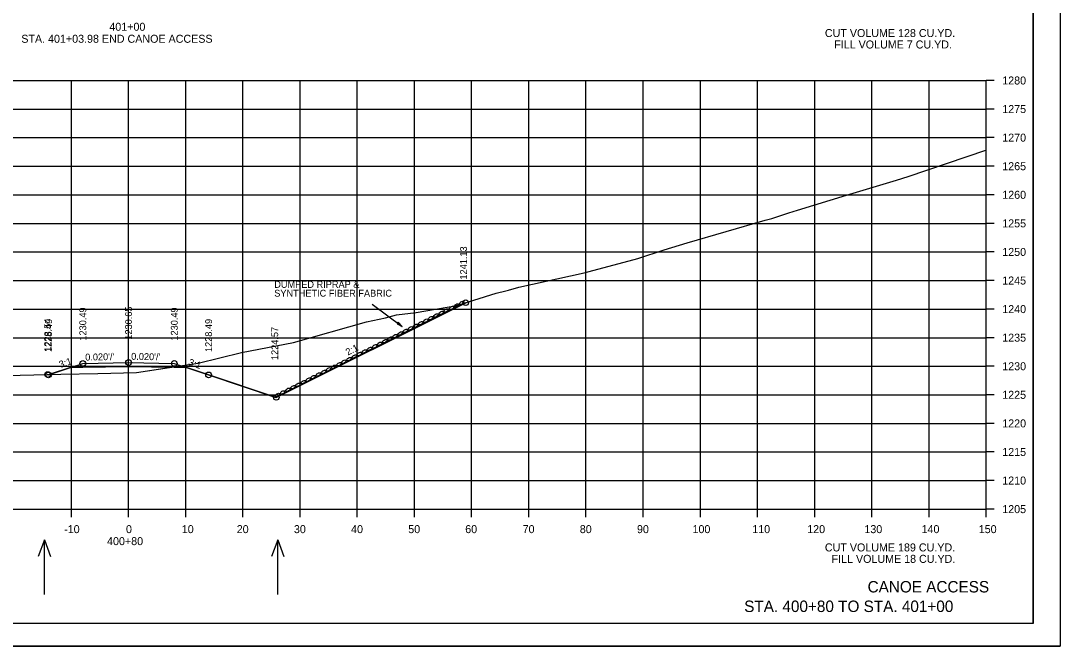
# Model space of a CAD drawing. Extents: x 1406028 to 1412453, y 321733 to 325986.
# Drawn here: x 1411764.4 to 1411946.2, y 322684.9 to 322794.4 of the extents above; entities that cross this region are included whole.
import ezdxf

# ---------------------------------------------------------------- set-up
doc = ezdxf.new("R2010")
doc.units = 0
for name, color, linetype in [('R_Alt Surface', 7, 'Continuous'), ('R_Axis', 7, 'Continuous'), ('R_Axis Annot', 7, 'Continuous'), ('R_Border', 7, 'Continuous'), ('R_Contours', 7, 'Continuous'), ('R_Draft', 7, 'Continuous'), ('R_Exist Surface', 7, 'Continuous'), ('R_Fin Surface', 7, 'Continuous'), ('R_Fin Surface Annot', 7, 'Continuous'), ('R_Grid', 7, 'Continuous'), ('R_No Plot', 7, 'Continuous'), ('R_Water Annot', 7, 'Continuous')]:
    doc.layers.add(name, color=color, linetype=linetype)

msp = doc.modelspace()

# ---------------------------------------------------------------- linework, layer by layer
for points in [[(1411809.08, 322728.49), (1411842.2, 322745.05)], [(1411797.24, 322732.44), (1411809.08, 322728.49)]]:
    msp.add_lwpolyline(points)
at = {"layer": 'R_Alt Surface'}
msp.add_lwpolyline([(1411773.11, 322733.7), (1411775.24, 322733.75), (1411783.24, 322733.91), (1411791.24, 322733.75), (1411793.38, 322733.7)], dxfattribs=at)
at = {"layer": 'R_Axis'}
for p, q in [((1411933.24, 322708.93), (1411933.24, 322783.93)), ((1411934.64, 322783.93), (1411933.24, 322783.93)), ((1411934.64, 322778.93), (1411933.24, 322778.93)), ((1411934.64, 322773.93), (1411933.24, 322773.93)), ((1411934.64, 322768.93), (1411933.24, 322768.93)), ((1411934.64, 322763.93), (1411933.24, 322763.93)), ((1411934.64, 322758.93), (1411933.24, 322758.93)), ((1411934.64, 322753.93), (1411933.24, 322753.93)), ((1411934.64, 322748.93), (1411933.24, 322748.93)), ((1411934.64, 322743.93), (1411933.24, 322743.93)), ((1411934.64, 322738.93), (1411933.24, 322738.93)), ((1411934.64, 322733.93), (1411933.24, 322733.93)), ((1411934.64, 322728.93), (1411933.24, 322728.93)), ((1411934.64, 322723.93), (1411933.24, 322723.93)), ((1411934.64, 322718.93), (1411933.24, 322718.93)), ((1411934.64, 322713.93), (1411933.24, 322713.93)), ((1411633.24, 322708.93), (1411933.24, 322708.93)), ((1411773.24, 322707.53), (1411773.24, 322708.93)), ((1411783.24, 322707.53), (1411783.24, 322708.93)), ((1411793.24, 322707.53), (1411793.24, 322708.93)), ((1411803.24, 322707.53), (1411803.24, 322708.93)), ((1411813.24, 322707.53), (1411813.24, 322708.93)), ((1411823.24, 322707.53), (1411823.24, 322708.93)), ((1411833.24, 322707.53), (1411833.24, 322708.93)), ((1411843.24, 322707.53), (1411843.24, 322708.93)), ((1411853.24, 322707.53), (1411853.24, 322708.93)), ((1411863.24, 322707.53), (1411863.24, 322708.93)), ((1411873.24, 322707.53), (1411873.24, 322708.93)), ((1411883.24, 322707.53), (1411883.24, 322708.93)), ((1411893.24, 322707.53), (1411893.24, 322708.93)), ((1411903.24, 322707.53), (1411903.24, 322708.93)), ((1411913.24, 322707.53), (1411913.24, 322708.93)), ((1411923.24, 322707.53), (1411923.24, 322708.93)), ((1411933.24, 322707.53), (1411933.24, 322708.93)), ((1411934.64, 322708.93), (1411933.24, 322708.93))]:
    msp.add_line(p, q, dxfattribs=at)
at = {"layer": 'R_Border'}
for q in [(1411941.42, 322894.39), (1411625.24, 322688.93)]:
    msp.add_line((1411941.42, 322688.93), q, dxfattribs=at)
at = {"layer": 'R_Contours'}
for points in [[(1411790.72, 322733.78), (1411795.4, 322734.49), (1411802.97, 322736.34), (1411812.06, 322738.07), (1411824.86, 322741.68), (1411828.19, 322742.38), (1411830.12, 322742.9), (1411833.52, 322743.32), (1411840.64, 322744.57), (1411842.2, 322745.05), (1411809.08, 322728.49), (1411797.24, 322732.44), (1411793.38, 322733.73), (1411791.24, 322733.77)], [(1411769.35, 322732.47), (1411771.39, 322732.52), (1411777.87, 322732.66), (1411784.62, 322732.85), (1411790.72, 322733.78), (1411783.24, 322733.93), (1411775.24, 322733.77), (1411773.11, 322733.73)], [(1411769.15, 322732.47), (1411769.35, 322732.47), (1411769.24, 322732.44)]]:
    msp.add_lwpolyline(points, close=True, dxfattribs=at)
at = {"layer": 'R_Draft'}
for p, q in [((1411825.87, 322744.82), (1411831.1, 322740.9)), ((1411830.39, 322741.62), (1411830.21, 322741.38)), ((1411830.21, 322741.38), (1411831.1, 322740.9)), ((1411830.23, 322741.4), (1411830.97, 322741)), ((1411830.24, 322741.42), (1411830.83, 322741.11)), ((1411830.26, 322741.44), (1411830.7, 322741.21)), ((1411830.27, 322741.46), (1411830.56, 322741.31)), ((1411830.29, 322741.48), (1411830.43, 322741.41)), ((1411830.32, 322741.52), (1411830.43, 322741.41)), ((1411830.33, 322741.54), (1411830.56, 322741.31)), ((1411830.35, 322741.56), (1411830.7, 322741.21)), ((1411830.36, 322741.58), (1411830.83, 322741.11)), ((1411830.38, 322741.6), (1411830.97, 322741)), ((1411830.39, 322741.62), (1411831.1, 322740.9))]:
    msp.add_line(p, q, dxfattribs=at)
for centre in [(1411841.5, 322745.01), (1411837.9, 322743.26), (1411838.8, 322743.7), (1411839.7, 322744.13), (1411840.6, 322744.57), (1411834.32, 322741.46), (1411835.22, 322741.9), (1411836.11, 322742.36), (1411837, 322742.81), (1411830.75, 322739.66), (1411831.64, 322740.11), (1411832.53, 322740.56), (1411833.43, 322741.01), (1411827.17, 322737.87), (1411828.07, 322738.32), (1411828.96, 322738.77), (1411829.85, 322739.21), (1411823.6, 322736.08), (1411824.49, 322736.52), (1411825.38, 322736.97), (1411826.28, 322737.42), (1411820.02, 322734.28), (1411820.91, 322734.73), (1411821.81, 322735.18), (1411822.7, 322735.63), (1411816.45, 322732.49), (1411817.34, 322732.94), (1411818.23, 322733.39), (1411819.13, 322733.83), (1411812.87, 322730.69), (1411813.76, 322731.14), (1411814.66, 322731.59), (1411815.55, 322732.04), (1411809.3, 322728.9), (1411810.19, 322729.35), (1411811.08, 322729.8), (1411811.98, 322730.25)]:
    msp.add_ellipse(centre, major_axis=(0.371, 0.232), ratio=0.517889, dxfattribs=at)
at = {"layer": 'R_Exist Surface'}
msp.add_lwpolyline([(1411759.48, 322732.23), (1411771.39, 322732.52), (1411777.87, 322732.66), (1411784.62, 322732.85), (1411795.4, 322734.49), (1411802.97, 322736.34), (1411812.06, 322738.07), (1411824.86, 322741.68), (1411828.19, 322742.38), (1411830.12, 322742.9), (1411833.52, 322743.32), (1411840.64, 322744.57), (1411847.54, 322746.69), (1411849.2, 322747.11), (1411849.67, 322747.27), (1411851.52, 322747.75), (1411862.94, 322750.27), (1411872.28, 322752.76), (1411876.91, 322754.28), (1411880.92, 322755.5), (1411894.59, 322759.47), (1411895.77, 322759.81), (1411898.73, 322760.75), (1411900.25, 322761.24), (1411908.8, 322763.86), (1411917.52, 322766.49), (1411919.58, 322767.15), (1411933.17, 322771.76), (1411933.24, 322771.78)], dxfattribs=at)
at = {"layer": 'R_Fin Surface'}
msp.add_lwpolyline([(1411769.09, 322732.47), (1411769.24, 322732.42), (1411773.11, 322733.7), (1411775.24, 322734.42), (1411783.24, 322734.58), (1411791.24, 322734.42), (1411793.38, 322733.7), (1411797.24, 322732.42), (1411809.01, 322728.49), (1411835.53, 322741.8), (1411837.82, 322742.96), (1411842.02, 322745)], dxfattribs=at)
at = {"layer": 'R_Grid'}
for p, q in [((1411633.24, 322783.93), (1411933.24, 322783.93)), ((1411773.24, 322708.93), (1411773.24, 322783.93)), ((1411783.24, 322708.93), (1411783.24, 322783.93)), ((1411793.24, 322708.93), (1411793.24, 322783.93)), ((1411803.24, 322708.93), (1411803.24, 322783.93)), ((1411813.24, 322708.93), (1411813.24, 322783.93)), ((1411823.24, 322708.93), (1411823.24, 322783.93)), ((1411833.24, 322708.93), (1411833.24, 322783.93)), ((1411843.24, 322708.93), (1411843.24, 322783.93)), ((1411853.24, 322708.93), (1411853.24, 322783.93)), ((1411863.24, 322708.93), (1411863.24, 322783.93)), ((1411873.24, 322708.93), (1411873.24, 322783.93)), ((1411883.24, 322708.93), (1411883.24, 322783.93)), ((1411893.24, 322708.93), (1411893.24, 322783.93)), ((1411903.24, 322708.93), (1411903.24, 322783.93)), ((1411913.24, 322708.93), (1411913.24, 322783.93)), ((1411923.24, 322708.93), (1411923.24, 322783.93)), ((1411933.24, 322708.93), (1411933.24, 322783.93)), ((1411633.24, 322778.93), (1411933.24, 322778.93)), ((1411633.24, 322773.93), (1411933.24, 322773.93)), ((1411633.24, 322768.93), (1411933.24, 322768.93)), ((1411633.24, 322763.93), (1411933.24, 322763.93)), ((1411633.24, 322758.93), (1411933.24, 322758.93)), ((1411633.24, 322753.93), (1411933.24, 322753.93)), ((1411633.24, 322748.93), (1411933.24, 322748.93)), ((1411633.24, 322743.93), (1411933.24, 322743.93)), ((1411633.24, 322738.93), (1411933.24, 322738.93)), ((1411633.24, 322733.93), (1411933.24, 322733.93)), ((1411633.24, 322728.93), (1411933.24, 322728.93)), ((1411633.24, 322723.93), (1411933.24, 322723.93)), ((1411633.24, 322718.93), (1411933.24, 322718.93)), ((1411633.24, 322713.93), (1411933.24, 322713.93)), ((1411633.24, 322708.93), (1411933.24, 322708.93))]:
    msp.add_line(p, q, dxfattribs=at)
at = {"layer": 'R_No Plot'}
msp.add_line((1411612.84, 322684.95), (1411946.18, 322684.95), dxfattribs=at)
for points in [[(1411612.84, 322898.28), (1411946.18, 322898.28), (1411946.18, 322684.94), (1411612.84, 322684.94)], [(1411859.16, 322894.39), (1411878.78, 322894.39), (1411878.78, 322884.51), (1411894.9, 322884.51), (1411918.1, 322884.51), (1411918.1, 322860.17), (1411941.42, 322860.17), (1411941.42, 322688.93), (1411625.24, 322688.93), (1411625.24, 322894.39)]]:
    msp.add_lwpolyline(points, close=True, dxfattribs=at)
for centre in [(1411842.2, 322745.05), (1411775.24, 322734.42), (1411775.24, 322734.42), (1411783.24, 322734.58), (1411791.24, 322734.42), (1411791.24, 322734.42), (1411769.09, 322732.47), (1411769.09, 322732.47), (1411769.24, 322732.42), (1411797.24, 322732.42), (1411809.08, 322728.49)]:
    msp.add_circle(centre, 0.5, dxfattribs=at)
at = {"layer": 'R_Water Annot'}
for p, q in [((1411768.51, 322703.56), (1411767.45, 322700.63)), ((1411768.51, 322693.98), (1411768.51, 322703.56)), ((1411768.51, 322703.56), (1411769.58, 322700.63)), ((1411809.32, 322703.56), (1411808.26, 322700.63)), ((1411809.32, 322693.98), (1411809.32, 322703.56)), ((1411809.32, 322703.56), (1411810.39, 322700.63))]:
    msp.add_line(p, q, dxfattribs=at)

# ---------------------------------------------------------------- texts
at = {"layer": 'R_Axis Annot'}
for s, p in [('401+00', (1411779.88, 322792.63)), ('CUT VOLUME 128 CU.YD.', (1411905.02, 322791.53)), ('STA. 401+03.98 END CANOE ACCESS', (1411764.48, 322790.53)), ('FILL VOLUME 7 CU.YD.', (1411906.65, 322789.53)), ('1280', (1411936.04, 322783.23)), ('1275', (1411936.04, 322778.23)), ('1270', (1411936.04, 322773.23)), ('1265', (1411936.04, 322768.23)), ('1260', (1411936.04, 322763.23)), ('1255', (1411936.04, 322758.23)), ('1250', (1411936.04, 322753.23)), ('1245', (1411936.04, 322748.23)), ('1240', (1411936.04, 322743.23)), ('1235', (1411936.04, 322738.23)), ('1230', (1411936.04, 322733.23)), ('1225', (1411936.04, 322728.23)), ('1220', (1411936.04, 322723.23)), ('1215', (1411936.04, 322718.23)), ('1210', (1411936.04, 322713.23)), ('1205', (1411936.04, 322708.23)), ('-10', (1411771.98, 322704.73)), ('0', (1411782.79, 322704.73)), ('10', (1411792.55, 322704.73)), ('20', (1411802.16, 322704.73)), ('30', (1411812.16, 322704.73)), ('40', (1411822.16, 322704.73)), ('50', (1411832.16, 322704.73)), ('60', (1411842.12, 322704.73)), ('70', (1411852.16, 322704.73)), ('80', (1411862.16, 322704.73)), ('90', (1411872.16, 322704.73)), ('100', (1411881.87, 322704.73)), ('110', (1411892.32, 322704.73)), ('120', (1411901.93, 322704.73)), ('130', (1411911.93, 322704.73)), ('140', (1411921.93, 322704.73)), ('150', (1411931.93, 322704.73)), ('400+80', (1411779.48, 322702.63)), ('CUT VOLUME 189 CU.YD.', (1411905.02, 322701.53)), ('FILL VOLUME 18 CU.YD.', (1411906.19, 322699.53))]:
    msp.add_text(s, height=1.4, dxfattribs=at).set_placement(p)
at = {"layer": 'R_Draft'}
for s, height, p in [('SYNTHETIC FIBER FABRIC', 1.2, (1411808.72, 322746.11)), ('DUMPED RIPRAP &', 1.2, (1411808.72, 322747.65)), ('CANOE ACCESS', 2, (1411912.49, 322694.35)), ('STA. 400+80 TO STA. 401+00', 2, (1411890.91, 322690.93))]:
    msp.add_text(s, height=height, dxfattribs=at).set_placement(p)
at = {"layer": 'R_Fin Surface Annot'}
for s, rotation, p in [('1241.13', 90, (1411842.42, 322749.1)), ('1230.49', 90, (1411775.84, 322738.42)), ('1230.65', 90, (1411783.84, 322738.58)), ('1230.49', 90, (1411791.84, 322738.42)), ('1228.54', 90, (1411769.69, 322736.47)), ('1228.49', 90, (1411769.84, 322736.42)), ('1228.49', 90, (1411797.84, 322736.42)), ('1224.57', 90, (1411809.41, 322735.01)), ("0.020'/'", 1.1458, (1411775.67, 322734.92)), ("0.020'/'", 358.8542, (1411783.69, 322735.07)), ('2:1', 26.5651, (1411821.57, 322735.79)), ('3:1', 18.4349, (1411771.3, 322733.63)), ('3:1', 341.5651, (1411793.61, 322734.15))]:
    msp.add_text(s, height=1.2, rotation=rotation, dxfattribs=at).set_placement(p)

doc.saveas('drawing.dxf')
